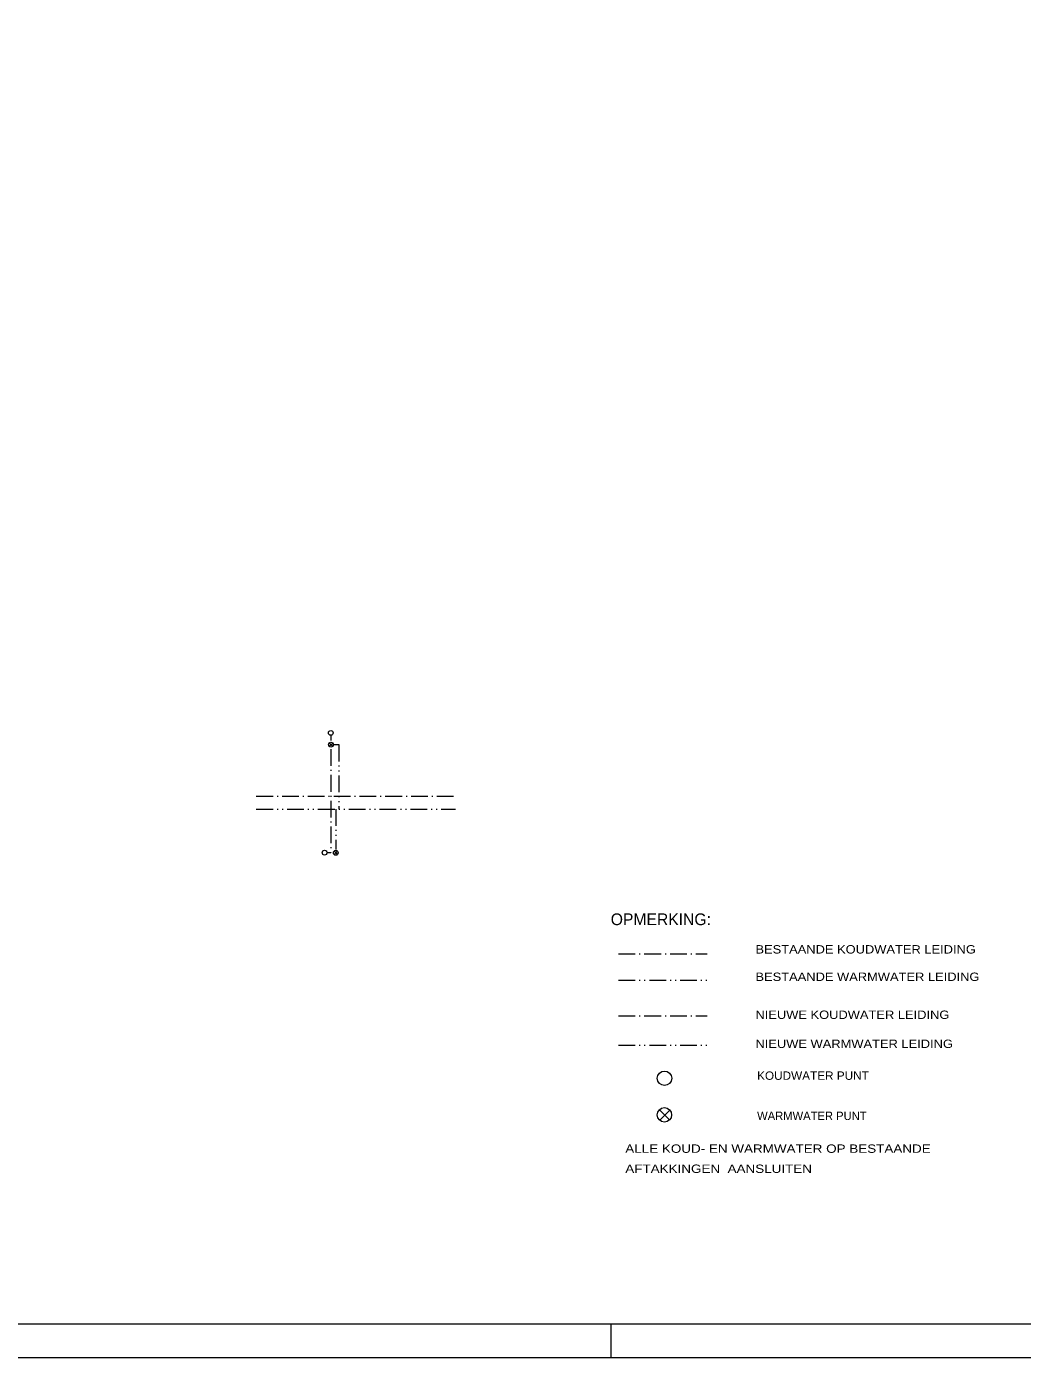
# Model space of a CAD drawing. Extents: x 295824 to 414724, y 24924 to 109024.
# Drawn here: x 355274 to 384999, y 24924 to 64629 of the extents above; entities that cross this region are included whole.
import ezdxf

# ---------------------------------------------------------------- set-up
doc = ezdxf.new("R2010")
doc.units = 0
doc.header["$LTSCALE"] = 100
doc.linetypes.add('DASH_DOUBLE_DOT', pattern=[9.2, 5, -1.2, 0.3, -1.2, 0.3, -1.2])
doc.linetypes.add('DOT_DASHED', pattern=[7.7, 5, -1.2, 0.3, -1.2])
for name, color, linetype, lineweight in [('1', 7, 'Continuous', 13), ('16', 7, 'Continuous', 13), ('30', 7, 'Continuous', 13)]:
    doc.layers.add(name, color=color, linetype=linetype, lineweight=lineweight)

msp = doc.modelspace()

# ---------------------------------------------------------------- linework, layer by layer
at = {"layer": '1'}
for p, q in [((372723.6, 24923.8), (372723.6, 25923.8)), ((304995.6, 24923.8), (414723.6, 24923.8))]:
    msp.add_line(p, q, dxfattribs=at)
msp.add_lwpolyline([(304995.6, 25923.8), (413723.6, 25923.8), (413723.6, 108023.8), (304995.6, 108023.8)], dxfattribs=at)
at = {"layer": '1', "linetype": 'DASH_DOUBLE_DOT'}
msp.add_lwpolyline([(364428.5, 43205.9), (364596, 43205.9), (364596, 41290)], dxfattribs=at)
at = {"layer": '30', "linetype": 'DOT_DASHED'}
for p, q in [((364352.2, 43491.6), (364352.2, 43332.4)), ((364352.2, 43072.3), (364352.2, 39981.8)), ((362130.1, 41666.4), (368076.5, 41666.4)), ((364352.2, 39981.8), (364245.9, 39981.8)), ((372942.7, 36962.9), (375584.3, 36962.9)), ((372942.7, 35109.5), (375584.3, 35109.5))]:
    msp.add_line(p, q, dxfattribs=at)
at = {"layer": '30'}
for p, q in [((364408.5, 43156.2), (364307.2, 43257.5)), ((364410.6, 43253.3), (364309.4, 43152.2)), ((364553.7, 39928), (364452.4, 40029.3)), ((364555.8, 40025.1), (364454.7, 39924)), ((374468.1, 32010.6), (374164.1, 32314.6)), ((374474.4, 32302), (374170.9, 31998.6))]:
    msp.add_line(p, q, dxfattribs=at)
at = {"layer": '30', "linetype": 'DASH_DOUBLE_DOT'}
for p, q in [((362130.1, 41283.1), (368076.5, 41283.1)), ((364502.1, 41283.1), (364502.1, 40074.8)), ((372942.7, 36176.2), (375584.3, 36176.2)), ((372942.7, 34242.9), (375584.3, 34242.9))]:
    msp.add_line(p, q, dxfattribs=at)
at = {"layer": '30'}
for centre, radius in [((364352.2, 43556.3), 71.7), ((364356.9, 43205.9), 71.7), ((364169, 39981.8), 71.7), ((364502.1, 39977.7), 71.7), ((374315.3, 33252.1), 215), ((374313.2, 32159.7), 215)]:
    msp.add_circle(centre, radius, dxfattribs=at)

# ---------------------------------------------------------------- texts
at = {"layer": '16'}
for s, height, p in [('OPMERKING:', 350, (372710.8, 37820.3)), ('WARMWATER PUNT', 250, (377079.8, 32005.2))]:
    msp.add_text(s, height=height, dxfattribs=at).set_placement(p)
for s, width, p in [('BESTAANDE KOUDWATER LEIDING', 1.15, (377030.6, 36973.2)), ('BESTAANDE WARMWATER LEIDING', 1.15, (377030.6, 36155)), ('NIEUWE KOUDWATER LEIDING', 1.15, (377030.6, 35021.7)), ('NIEUWE WARMWATER LEIDING', 1.15, (377030.6, 34155)), ('KOUDWATER PUNT', 1.05, (377079.8, 33205.2)), ('ALLE KOUD- EN WARMWATER OP BESTAANDE ', 1.2, (373144.8, 31027)), ('AFTAKKINGEN  AANSLUITEN', 1.2, (373144.8, 30427))]:
    msp.add_text(s, height=250, dxfattribs=dict(at, width=width)).set_placement(p)

doc.saveas('drawing.dxf')
